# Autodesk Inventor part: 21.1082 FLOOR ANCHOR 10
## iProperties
Created: 2007-04
Part Number: 21.1082 FLOOR ANCHOR 10
Material: Steel
Document SubType Name: Modeling
Designer: Andy Moles
Density: 7.85 g/cm^3
Author: Andy Moles
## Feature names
1. Extrusion1
2. Extrusion2
3. Extrusion3
4. Extrusion4
5. Extrusion5
6. Extrusion6
7. Extrusion7
8. Revolution1
9. Fillet1
10. Chamfer1
